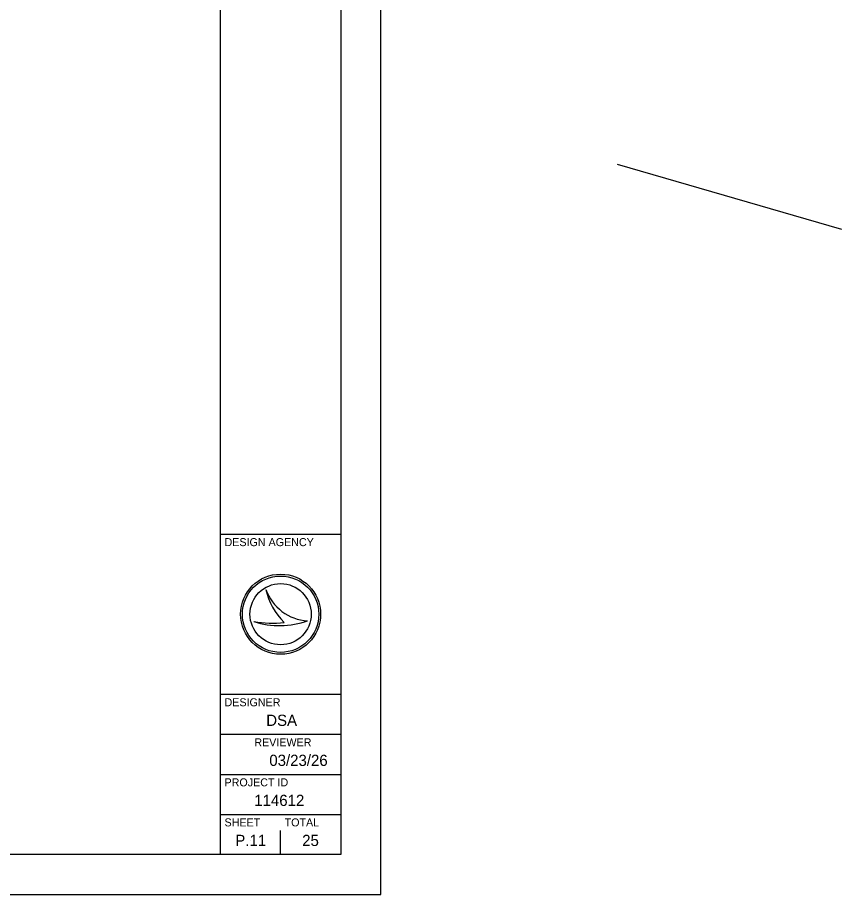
# Model space of a CAD drawing. Extents: x -66 to 795, y 0 to 440.
# Drawn here: x 589.3 to 795, y 0 to 219 of the extents above; entities that cross this region are included whole.
import ezdxf

# ---------------------------------------------------------------- set-up
doc = ezdxf.new("R2010")
doc.units = 0
for name, color, linetype in [('RD_P_Fence', 7, 'Continuous'), ('SH_Border', 7, 'Continuous'), ('SH_Cut_Line', 7, 'Continuous'), ('SH_Data', 7, 'Continuous')]:
    doc.layers.add(name, color=color, linetype=linetype)

msp = doc.modelspace()

# ---------------------------------------------------------------- linework, layer by layer
at = {"layer": 'RD_P_Fence'}
msp.add_lwpolyline([(739.03, 182.42), (795.04, 166.19)], dxfattribs=at)
at = {"layer": 'SH_Border'}
for p, q in [((640, 10), (640, 430)), ((640, 90), (670, 90)), ((640, 50), (670, 50)), ((640, 40), (670, 40)), ((640, 30), (670, 30)), ((640, 20), (670, 20))]:
    msp.add_line(p, q, dxfattribs=at)
msp.add_lwpolyline([(30, 430), (670, 430), (670, 10), (30, 10)], close=True, dxfattribs=at)
at = {"layer": 'SH_Cut_Line'}
msp.add_lwpolyline([(0, 0), (680, 0), (680, 440), (0, 440)], close=True, dxfattribs=at)
at = {"layer": 'SH_Data'}
for p, q in [((651.35, 76.19), (651.35, 76.19)), ((648.34, 68.19), (648.34, 68.19)), ((655, 70), (655, 70)), ((661.75, 68.37), (661.75, 68.37)), ((655, 10), (655, 16)), ((647.5, 13.5), (647.5, 13.5))]:
    msp.add_line(p, q, dxfattribs=at)
for radius in [10, 9.54, 9.54, 7.64]:
    msp.add_circle((655, 70), radius, dxfattribs=at)
for centre, radius, start, end in [((662.32, 79.95), 11.6, 198.9257, 198.9319), ((666.93, 79.4), 15.91, 191.6379, 191.6421), ((662.32, 79.95), 11.6, 198.9319, 267.1657), ((666.93, 79.4), 15.91, 191.6421, 226.0947), ((654.79, 87.4), 20.26, 251.4576, 290.0832), ((652.96, 93.09), 25.32, 259.4964, 259.4995), ((654.79, 87.4), 20.26, 251.4527, 251.4576), ((652.96, 93.09), 25.32, 259.4995, 276.6672)]:
    msp.add_arc(centre, radius, start, end, dxfattribs=at)

# ---------------------------------------------------------------- texts
for s, height, p in [('DESIGN AGENCY', 2, (641, 87)), ('DESIGNER', 2, (641, 47)), ('DSA', 2.8, (651.41, 42.1)), ('REVIEWER', 2, (648.44, 37)), ('03/23/26', 2.8, (652.18, 32.1)), ('PROJECT ID', 2, (641, 27)), ('114612', 2.8, (648.42, 22.1)), ('SHEET', 2, (641, 17)), ('TOTAL', 2, (656, 17)), ('P.11', 2.8, (643.69, 12.1)), ('25', 2.8, (660.39, 12.1))]:
    msp.add_text(s, height=height, dxfattribs=at).set_placement(p)

doc.saveas('drawing.dxf')
